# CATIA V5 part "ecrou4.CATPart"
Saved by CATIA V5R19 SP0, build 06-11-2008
Part number: ecrou4
Definition: NONE
Nomenclature: 1
Source: Unknown
Description: PART-1-DESC
Bounding box of the stored display mesh (mm): x -4.041 to 4.041, y 0 to 3.2, z -3.5 to 3.5
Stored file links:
  G:\EU_thinkMotion\CFAO_2010\MMS_groupe3\MMS_groupe3\A reprendre\ftixier\florent-tixier\florent-tixier\ecrou4.CATPart
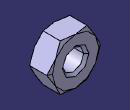
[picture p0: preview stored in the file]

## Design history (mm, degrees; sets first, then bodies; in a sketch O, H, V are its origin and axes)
Body1 "1" (main body)
  Solid1: solid without history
